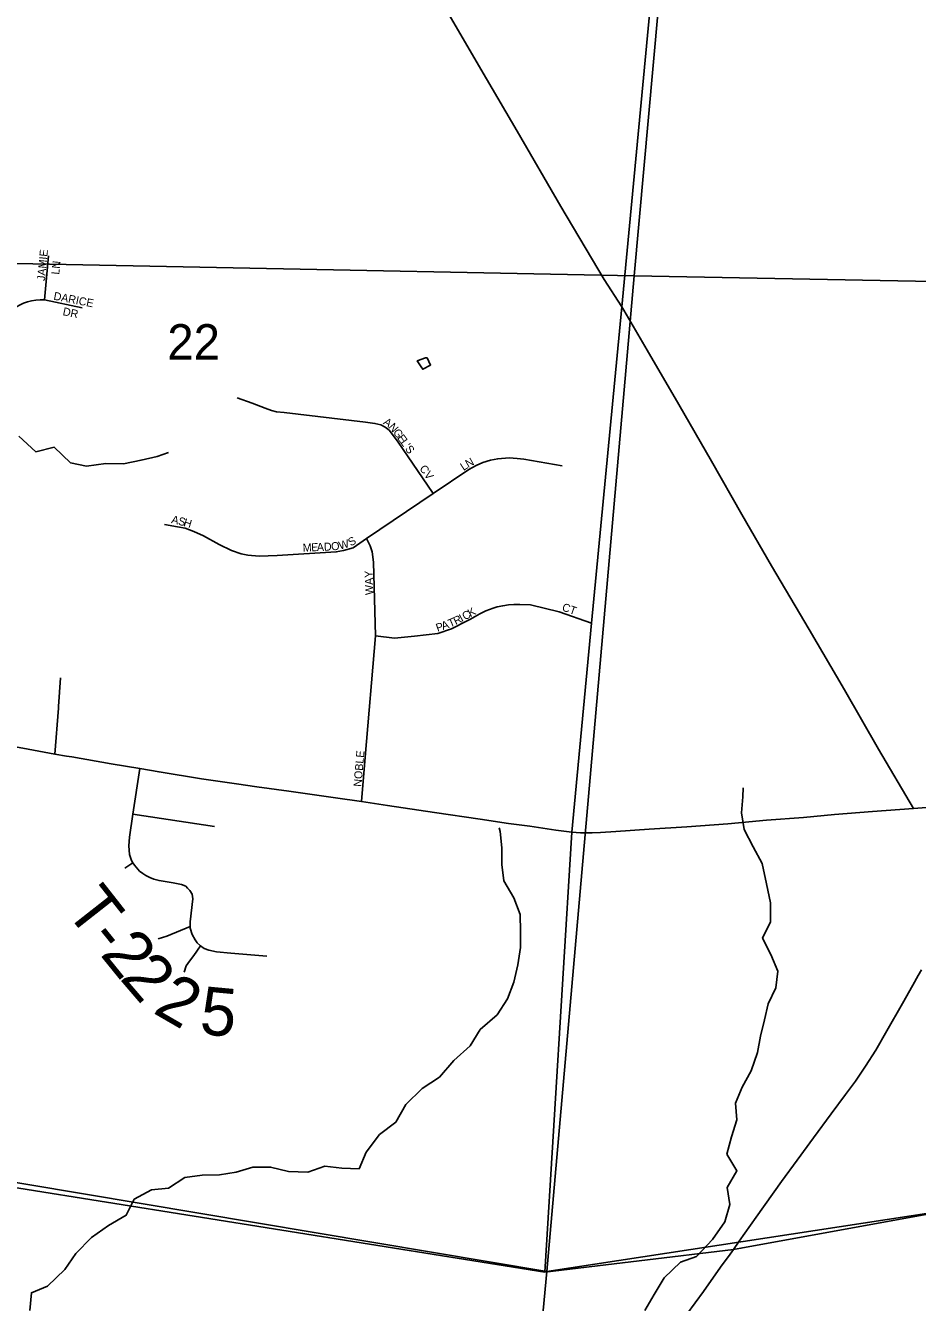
# Model space of a CAD drawing. Extents: x 0 to 1064, y 0 to 440.
# Drawn here: x 189.05 to 205.93, y 292.66 to 316.83 of the extents above; entities that cross this region are included whole.
import ezdxf

# ---------------------------------------------------------------- set-up
doc = ezdxf.new("R2010")
doc.units = 0
for name, color, linetype in [('GM_X_Minor_Lake', 7, 'Continuous'), ('GM_X_Minor_River', 7, 'Continuous'), ('GM_X_Section', 7, 'Continuous'), ('GM_X_Section_Text', 7, 'Continuous'), ('GM_X_State_Route', 7, 'Continuous'), ('GM_X_Township', 7, 'Continuous'), ('GM_X_Township_Road', 7, 'Continuous'), ('GM_X_Township_Road_Text', 7, 'Continuous'), ('GM_X_Township_Subdivision', 7, 'Continuous'), ('GM_X_Township_Subdivision_Text', 7, 'Continuous')]:
    doc.layers.add(name, color=color, linetype=linetype)

msp = doc.modelspace()

# ---------------------------------------------------------------- linework, layer by layer
at = {"layer": 'GM_X_Minor_Lake'}
for points in [[(196.65, 310.544), (196.622, 310.54), (196.464, 310.485), (196.553, 310.35)], [(196.553, 310.35), (196.568, 310.327), (196.719, 310.406), (196.65, 310.544)]]:
    msp.add_lwpolyline(points, dxfattribs=at)
at = {"layer": 'GM_X_Minor_River'}
for points in [[(188.928, 309.062), (189.25, 308.764), (189.596, 308.849), (189.905, 308.557), (190.208, 308.49), (190.572, 308.545), (190.906, 308.533), (191.24, 308.606), (191.543, 308.672), (191.762, 308.752)], [(200.772, 292.512), (200.948, 292.816), (201.136, 293.126), (201.445, 293.424), (201.749, 293.534), (202.052, 293.856), (202.283, 294.19), (202.38, 294.519), (202.331, 294.841), (202.513, 295.151), (202.325, 295.468), (202.41, 295.796), (202.513, 296.119), (202.489, 296.435), (202.61, 296.739), (202.786, 297.049), (202.902, 297.396), (202.962, 297.706), (203.035, 298.01), (203.102, 298.314), (203.248, 298.618), (203.29, 298.935), (203.157, 299.251), (202.999, 299.555), (203.151, 299.865), (203.151, 300.224), (203.072, 300.589), (202.993, 300.972), (202.823, 301.289), (202.653, 301.617), (202.599, 301.927), (202.623, 302.231), (202.629, 302.402)], [(191.44, 294.793), (191.761, 294.829), (192.071, 295.03), (192.398, 295.072), (192.726, 295.079), (193.041, 295.127), (193.357, 295.224), (193.691, 295.224), (194.03, 295.139), (194.395, 295.127), (194.716, 295.243), (195.038, 295.206), (195.365, 295.194), (195.499, 295.51), (195.754, 295.839), (196.063, 296.076), (196.251, 296.411), (196.561, 296.715), (196.888, 296.928), (197.155, 297.244), (197.465, 297.518), (197.653, 297.828), (197.975, 298.108), (198.175, 298.412), (198.29, 298.728), (198.369, 299.05), (198.418, 299.379), (198.418, 299.683), (198.412, 300.005), (198.29, 300.321), (198.102, 300.644), (198.066, 300.954), (198.066, 301.27), (198.036, 301.574), (198.017, 301.647)], [(189.134, 292.512), (189.164, 292.846), (189.467, 292.974), (189.795, 293.284), (190.007, 293.588), (190.305, 293.892), (190.626, 294.118), (190.96, 294.312), (191.112, 294.616), (191.44, 294.793)]]:
    msp.add_lwpolyline(points, dxfattribs=at)
at = {"layer": 'GM_X_Section'}
for points in [[(185.631, 328.553), (201.835, 326.137), (200.572, 312.097), (184.126, 312.421), (184.993, 320.578)], [(201.835, 326.137), (219.098, 327.846), (217.525, 311.775), (200.572, 312.097)], [(200.572, 312.097), (198.919, 293.248), (182.468, 296.009), (184.126, 312.421)], [(217.525, 311.775), (215.966, 295.854), (198.919, 293.248), (200.572, 312.097)], [(182.468, 296.009), (198.919, 293.248), (197.538, 278.526), (180.874, 279.765)], [(215.966, 295.854), (214.149, 277.17), (197.538, 278.526), (198.919, 293.248)]]:
    msp.add_lwpolyline(points, close=True, dxfattribs=at)
at = {"layer": 'GM_X_State_Route'}
for points in [[(205.855, 302.014), (205.192, 303.133), (204.548, 304.258), (203.878, 305.398), (203.17, 306.608), (202.609, 307.579), (202.032, 308.586), (201.413, 309.656), (200.818, 310.689), (200.373, 311.443), (200.333, 311.506), (200.002, 312.027), (199.182, 313.404), (198.357, 314.835), (197.777, 315.824), (196.963, 317.218)], [(187.288, 303.461), (187.301, 303.459), (188.042, 303.325), (189.004, 303.151), (189.611, 303.043), (189.827, 303.005), (189.932, 302.987)], [(189.932, 302.987), (190.675, 302.857), (191.214, 302.767), (191.582, 302.705), (192.382, 302.575), (193.045, 302.48), (193.431, 302.423), (194.038, 302.341), (194.918, 302.215), (195.408, 302.145), (195.9, 302.072), (196.793, 301.939), (197.655, 301.812), (198.195, 301.731), (198.596, 301.679), (199.085, 301.605), (199.388, 301.565), (199.553, 301.554), (199.777, 301.55), (199.934, 301.555), (200.22, 301.574), (200.852, 301.618), (201.566, 301.668), (202.339, 301.725), (203.075, 301.79), (203.772, 301.842), (204.357, 301.896), (205.078, 301.958), (205.855, 302.014), (206.343, 302.048)], [(201.252, 292.01), (201.882, 292.872), (202.205, 293.33), (202.387, 293.58), (202.449, 293.668), (202.558, 293.824), (202.878, 294.28), (203.359, 294.953), (203.654, 295.354), (203.96, 295.778), (204.299, 296.233), (204.566, 296.596), (204.759, 296.854), (204.947, 297.133), (205.142, 297.436), (205.352, 297.801), (205.646, 298.32), (205.84, 298.668), (205.944, 298.851), (206.004, 298.961)]]:
    msp.add_lwpolyline(points, dxfattribs=at)
at = {"layer": 'GM_X_Township'}
for points in [[(203.722, 347.141), (202.693, 335.755), (202.695, 335.639), (202.632, 334.798), (202.075, 329.83), (201.215, 320.785), (201.099, 319.586), (200.333, 311.506), (199.764, 305.521), (199.388, 301.565), (198.877, 293.237), (187.261, 295.09), (182.432, 295.909), (172.793, 296.856), (149.277, 299.165)], [(227.814, 292.902), (215.892, 295.803), (207.617, 294.604), (202.589, 293.69), (202.449, 293.668), (198.877, 293.237), (199.388, 301.565), (199.764, 305.521), (200.333, 311.506), (201.099, 319.586), (201.215, 320.785), (202.075, 329.83), (202.632, 334.798), (202.695, 335.639), (202.693, 335.755), (203.722, 347.141)], [(132.309, 292.479), (132.404, 293.708), (132.476, 294.635), (132.789, 298.696), (132.878, 300.691), (132.881, 300.737), (132.884, 300.775), (143.744, 299.709), (149.277, 299.165), (172.793, 296.856), (182.432, 295.909), (187.261, 295.09), (198.877, 293.237), (202.449, 293.668), (202.589, 293.69), (207.617, 294.604), (215.892, 295.803), (227.814, 292.902), (227.881, 292.885), (232.24, 291.824)]]:
    msp.add_lwpolyline(points, dxfattribs=at)
at = {"layer": 'GM_X_Township_Road'}
for points in [[(189.68, 303.945), (189.713, 304.488)], [(189.611, 303.043), (189.678, 303.912), (189.68, 303.945)], [(193.619, 299.216), (192.94, 299.273), (192.67, 299.299), (192.52, 299.33), (192.437, 299.362), (192.364, 299.413), (192.302, 299.47), (192.261, 299.527), (192.204, 299.626), (192.168, 299.745), (192.168, 299.776), (192.168, 299.87), (192.219, 300.305), (192.204, 300.388), (192.162, 300.461), (192.121, 300.507), (192.084, 300.544), (192.007, 300.575), (191.846, 300.606), (191.582, 300.647), (191.483, 300.673), (191.405, 300.704), (191.328, 300.746), (191.276, 300.782), (191.213, 300.829), (191.115, 300.938), (191.086, 300.982), (191.058, 301.026), (191.022, 301.14), (191.006, 301.306), (191.022, 301.472), (191.084, 301.902), (191.214, 302.767)], [(191.084, 301.902), (192.629, 301.674)], [(190.933, 300.881), (191.086, 300.982)], [(191.561, 299.543), (191.727, 299.595), (192.168, 299.776)], [(192.053, 298.916), (192.095, 299.035), (192.157, 299.123), (192.24, 299.227), (192.364, 299.413)]]:
    msp.add_lwpolyline(points, dxfattribs=at)
at = {"layer": 'GM_X_Township_Subdivision'}
for points in [[(189.412, 311.642), (189.49, 312.475)], [(188.584, 311.182), (188.636, 311.258), (188.694, 311.33), (188.756, 311.397), (188.824, 311.459), (188.885, 311.505), (188.95, 311.545), (189.018, 311.578), (189.09, 311.603), (189.169, 311.621), (189.25, 311.634), (189.331, 311.641), (189.412, 311.642), (190.128, 311.491)], [(196.768, 307.977), (196.09, 308.966), (195.935, 309.171), (195.861, 309.228), (195.776, 309.273), (195.665, 309.302), (195.489, 309.326), (193.948, 309.506), (193.8, 309.522), (193.71, 309.543), (193.588, 309.588), (193.342, 309.682), (193.056, 309.788)], [(191.685, 307.385), (191.929, 307.343), (192.073, 307.317), (192.241, 307.257), (192.42, 307.173), (192.718, 307.012), (192.951, 306.893), (193.136, 306.833), (193.262, 306.809), (193.477, 306.785), (193.817, 306.803), (194.934, 306.869), (195.071, 306.893), (195.25, 306.946), (195.508, 307.124), (196.768, 307.977), (197.442, 308.431), (197.577, 308.504), (197.708, 308.559), (197.852, 308.605), (197.99, 308.633), (198.207, 308.648), (198.357, 308.639), (198.482, 308.624), (199.208, 308.5)], [(195.408, 302.145), (195.477, 302.985), (195.673, 305.283), (195.639, 306.677), (195.615, 306.868), (195.572, 306.986), (195.508, 307.124)], [(195.673, 305.283), (196.032, 305.239), (196.412, 305.274), (196.854, 305.326), (197.116, 305.412), (197.204, 305.455), (197.311, 305.512), (197.461, 305.592), (197.559, 305.644), (197.649, 305.697), (197.765, 305.752), (197.902, 305.804), (197.98, 305.827), (198.083, 305.85), (198.189, 305.866), (198.293, 305.874), (198.406, 305.875), (198.608, 305.865), (199.148, 305.734), (199.764, 305.521)]]:
    msp.add_lwpolyline(points, dxfattribs=at)

# ---------------------------------------------------------------- texts
at = {"layer": 'GM_X_Section_Text'}
msp.add_text('22', height=0.6697, rotation=0, dxfattribs=at).set_placement((191.736, 310.509))
at = {"layer": 'GM_X_Township_Road_Text'}
for s, rotation, p in [('T', 308.1257, (189.787, 300.087)), ('-', 308.9786, (190.216, 299.54)), ('2', 309.0254, (190.452, 299.249)), ('2', 310.5995, (190.822, 298.793)), ('2', 329.9759, (191.443, 298.155)), ('5', 354.6412, (192.331, 297.746))]:
    msp.add_text(s, height=0.909, rotation=rotation, dxfattribs=at).set_placement(p)
at = {"layer": 'GM_X_Township_Subdivision_Text'}
for s, height, rotation, p in [('JAMIE', 0.1515, 84.4251, (189.421, 311.992)), ('LN', 0.1515, 83.9832, (189.691, 312.112)), ('DARICE', 0.1515, 348.9037, (189.575, 311.644)), ('DR', 0.1515, 348.1183, (189.749, 311.352)), ('A', 0.152, 326.025, (195.809, 309.295)), ('N', 0.152, 311.1489, (195.912, 309.227)), ('G', 0.152, 306.5159, (195.998, 309.13)), ('E', 0.152, 306.154, (196.077, 309.023)), ('L', 0.152, 306.1158, (196.14, 308.937)), ('S', 0.152, 306.1158, (196.226, 308.818)), ("'", 0.152, 306.1758, (196.203, 308.85)), ('N', 0.152, 29.2542, (197.428, 308.456)), ('CV', 0.1515, 306.2589, (196.499, 308.446)), ('L', 0.152, 32.5382, (197.34, 308.399)), ('A', 0.152, 346.3402, (191.803, 307.417)), ('S', 0.152, 346.3502, (191.932, 307.386)), ('H', 0.152, 343.9225, (192.034, 307.361)), ('M', 0.152, 2.5869, (194.302, 306.871)), ('E', 0.152, 2.5691, (194.462, 306.879)), ('A', 0.152, 2.6083, (194.568, 306.883)), ('D', 0.152, 2.5797, (194.702, 306.889)), ('O', 0.152, 5.0627, (194.842, 306.896)), ('W', 0.152, 14.7341, (195.002, 306.912)), ('S', 0.152, 28.2383, (195.206, 306.971)), ('WAY', 0.1515, 91.7347, (195.635, 306.055)), ('C', 0.152, 29.1198, (197.367, 305.571)), ('K', 0.152, 29.2577, (197.472, 305.63)), ('CT', 0.1515, 340.5606, (199.192, 305.763)), ('P', 0.152, 19.0051, (196.849, 305.354)), ('A', 0.152, 19.4742, (196.952, 305.389)), ('T', 0.152, 22.666, (197.086, 305.437)), ('R', 0.152, 26.2154, (197.194, 305.482)), ('I', 0.152, 28.8572, (197.308, 305.538)), ('NOBLE', 0.1515, 85.0284, (195.408, 302.419))]:
    msp.add_text(s, height=height, rotation=rotation, dxfattribs=at).set_placement(p)

doc.saveas('drawing.dxf')
